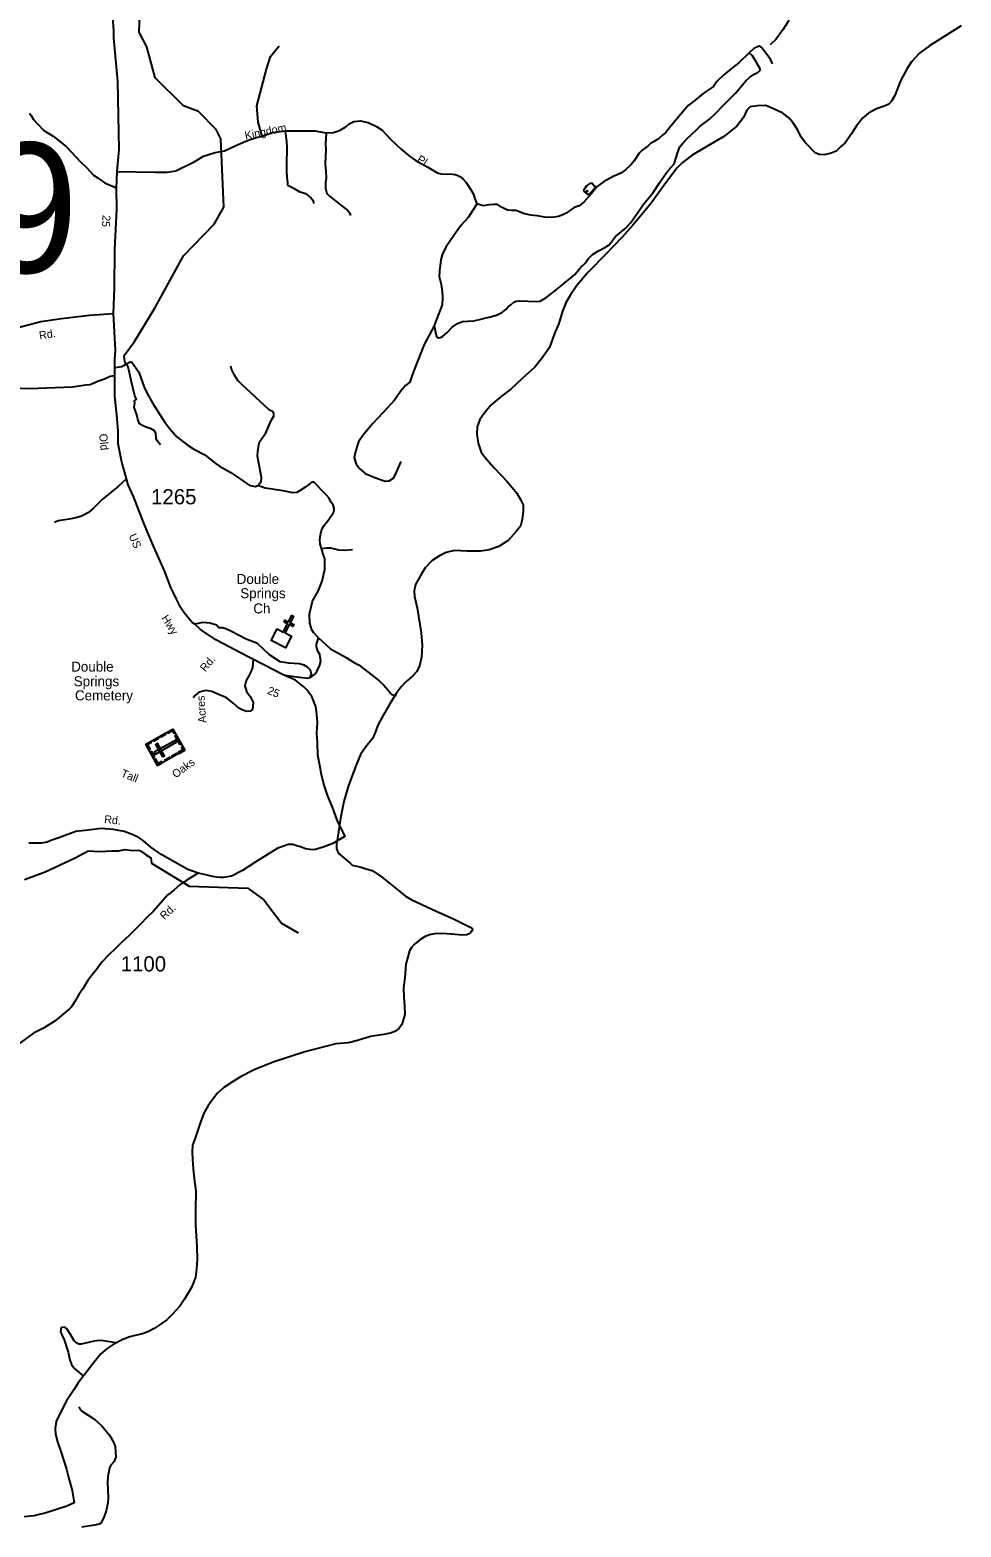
# Model space of a CAD drawing. Extents: x 884530 to 1028605, y 526725 to 653634.
# Drawn here: x 973414 to 981047, y 533743 to 546021 of the extents above; entities that cross this region are included whole.
import ezdxf

# ---------------------------------------------------------------- set-up
doc = ezdxf.new("R2010")
doc.units = 0
for name, color, linetype in [('Exist Boundary Political StateLine', 7, 'Continuous'), ('Exist Civil Recreational Trail or Greenway National Park', 7, 'Continuous'), ('Exist Cultural Cemetery CELL', 7, 'Continuous'), ('Exist Cultural Cemetery Label', 7, 'Continuous'), ('Exist Cultural Church CELL', 7, 'Continuous'), ('Exist Cultural Church Label', 7, 'Continuous'), ('Exist Hydrographic Creek Single Shore', 7, 'Continuous'), ('Exist Hydrographic Pond Under 1500 Sq Ft', 7, 'Continuous'), ('Exist Road Non-System Type 51', 7, 'Continuous'), ('Exist Road Non-System Type 51 Label', 7, 'Continuous'), ('Exist Road Primary NC Attributed', 7, 'Continuous'), ('Exist Road Secondary Structure Standard Bridge Number Label', 7, 'Continuous'), ('Exist Road Secondary Type 51 Attributed', 7, 'Continuous'), ('Exist Road Secondary Type 51 Label', 7, 'Continuous'), ('Exist Road Secondary Type 51 Number Label', 7, 'Continuous')]:
    doc.layers.add(name, color=color, linetype=linetype)

msp = doc.modelspace()

# ---------------------------------------------------------------- linework, layer by layer
at = {"layer": 'Exist Boundary Political StateLine'}
for points in [[(981047, 546056), (980900, 545961), (980789, 545891), (980707, 545830), (980640, 545760), (980605, 545705), (980551, 545603), (980503, 545483), (980477, 545438), (980456, 545414), (980426, 545399), (980353, 545374), (980288, 545340), (980238, 545298), (980215, 545266), (980190, 545235), (980150, 545169), (980097, 545096), (980058, 545062), (980023, 545027), (979982, 545010), (979925, 544996), (979884, 545000), (979852, 545013), (979773, 545096), (979737, 545143), (979709, 545200), (979669, 545263), (979632, 545303), (979587, 545340), (979510, 545375), (979447, 545401), (979377, 545400), (979319, 545390), (979292, 545364), (979264, 545303), (979209, 545233), (979102, 545147), (978957, 545064), (978843, 544994), (978763, 544934), (978721, 544890), (978627, 544767), (978499, 544591), (978357, 544420), (978269, 544323), (978132, 544180)], [(978132, 544180), (977993, 544037), (977897, 543926), (977845, 543849), (977808, 543783), (977780, 543716), (977750, 543613), (977713, 543532), (977673, 543417), (977615, 543335), (977552, 543255), (977446, 543159), (977355, 543074), (977280, 543018), (977191, 542944), (977134, 542872), (977101, 542827), (977081, 542767), (977078, 542705), (977088, 542633), (977113, 542560), (977142, 542517), (977217, 542432), (977327, 542318), (977404, 542222), (977436, 542170), (977457, 542128), (977457, 542076), (977449, 542006), (977435, 541952), (977399, 541908), (977334, 541834), (977257, 541785), (977178, 541757), (977107, 541746), (976997, 541747), (976893, 541751), (976827, 541735), (976770, 541709), (976712, 541671), (976654, 541609), (976625, 541562), (976574, 541474), (976564, 541422), (976566, 541374), (976587, 541283), (976622, 541078), (976630, 540976), (976623, 540878), (976606, 540806), (976585, 540759), (976552, 540724), (976496, 540674), (976456, 540633), (976415, 540579), (976364, 540494), (976300, 540385), (976266, 540320), (976250, 540274), (976226, 540213), (976167, 540141), (976125, 540078), (976086, 539986), (976022, 539818), (975988, 539693), (975961, 539558), (975943, 539442), (975926, 539343), (975928, 539309), (975934, 539287), (975951, 539262), (976038, 539187), (976056, 539172), (976081, 539167), (976129, 539156), (976179, 539140), (976218, 539127), (976296, 539076), (976347, 539036), (976450, 538954), (976493, 538917), (976538, 538889), (976708, 538811), (976897, 538725), (977023, 538664), (977042, 538650), (977037, 538630), (977019, 538610), (976996, 538601), (976962, 538598), (976867, 538606), (976793, 538610), (976729, 538608), (976690, 538600), (976654, 538587), (976611, 538559), (976566, 538524)], [(976566, 538524), (976543, 538497), (976524, 538468), (976514, 538428), (976496, 538361), (976486, 538247), (976477, 538165), (976480, 538089), (976484, 538019), (976488, 537947), (976463, 537865), (976442, 537834), (976411, 537811), (976378, 537796), (976316, 537784), (976205, 537766), (976100, 537734), (976025, 537714), (975921, 537706), (975666, 537641), (975409, 537556), (975253, 537493), (975139, 537437), (975073, 537395), (975002, 537348), (974948, 537299), (974904, 537241), (974873, 537194), (974840, 537137), (974812, 537064), (974772, 536941), (974747, 536876), (974743, 536822), (974747, 536758), (974753, 536682), (974763, 536577), (974774, 536501), (974775, 536459), (974770, 536377), (974771, 536223), (974781, 536044), (974785, 535938), (974778, 535860), (974770, 535790), (974737, 535709), (974680, 535613), (974642, 535555), (974583, 535489), (974536, 535444), (974474, 535398), (974433, 535372), (974390, 535349), (974344, 535331), (974233, 535303), (974174, 535281), (974096, 535241), (974047, 535209), (973996, 535163), (973941, 535095), (973809, 534925), (973778, 534876), (973714, 534778), (973674, 534704), (973630, 534609), (973620, 534553), (973623, 534505), (973640, 534443), (973671, 534355), (973713, 534218), (973732, 534141), (973759, 534042), (973777, 533941), (973716, 533916), (973548, 533859), (973447, 533835), (973367, 533826)]]:
    msp.add_lwpolyline(points, dxfattribs=at)
at = {"layer": 'Exist Civil Recreational Trail or Greenway National Park'}
msp.add_lwpolyline([(979635, 546099), (979585, 546021), (979528, 545943), (979483, 545898)], dxfattribs=at)
at = {"layer": 'Exist Cultural Cemetery CELL'}
for points in [[(974460, 539990), (974363, 540164), (974586, 540288), (974683, 540114)], [(974528, 540243), (974490, 540222), (974485, 540231), (974523, 540253)], [(974602, 540259), (974592, 540253), (974581, 540272), (974546, 540253), (974540, 540262), (974586, 540288)], [(974645, 540158), (974603, 540232), (974613, 540238), (974655, 540164)], [(974401, 540185), (974407, 540175), (974378, 540159), (974398, 540124), (974388, 540119), (974363, 540164)], [(974470, 540211), (974433, 540189), (974427, 540199), (974465, 540220)], [(974433, 540099), (974442, 540083), (974619, 540182), (974610, 540198)], [(974500, 540059), (974516, 540068), (974459, 540171), (974442, 540162)], [(974666, 540143), (974656, 540137), (974667, 540118), (974632, 540098), (974637, 540088), (974683, 540114)], [(974424, 540055), (974399, 540100), (974409, 540105), (974434, 540060)], [(974498, 540011), (974492, 540021), (974464, 540005), (974445, 540041), (974435, 540035), (974460, 539990)], [(974563, 540047), (974525, 540026), (974519, 540036), (974557, 540057)], [(974621, 540080), (974584, 540059), (974578, 540069), (974616, 540090)]]:
    msp.add_lwpolyline(points, close=True, dxfattribs=at)
at = {"layer": 'Exist Cultural Church CELL'}
msp.add_lwpolyline([(975440, 541109), (975491, 541083), (975526, 541151), (975497, 541166), (975504, 541180), (975533, 541166), (975560, 541219), (975574, 541212), (975547, 541158), (975576, 541144), (975568, 541130), (975540, 541144), (975505, 541076), (975557, 541050), (975508, 540955), (975392, 541014)], close=True, dxfattribs=at)
at = {"layer": 'Exist Hydrographic Creek Single Shore'}
for points in [[(974485, 542618), (974456, 542652), (974448, 542671), (974447, 542715), (974436, 542733), (974401, 542753), (974371, 542761), (974348, 542772), (974332, 542781), (974312, 542791), (974298, 542829), (974291, 542864), (974280, 542894), (974267, 542928), (974275, 542960), (974272, 542979), (974286, 542992), (974274, 543021), (974243, 543146), (974226, 543222), (974218, 543255), (974195, 543291), (974188, 543323), (974185, 543351), (974272, 543466), (974441, 543745), (974672, 544170), (974923, 544428), (975003, 544567), (974980, 545129), (974941, 545205), (974796, 545352), (974673, 545398), (974439, 545629), (974373, 545883), (974310, 546002), (974329, 546543)], [(973369, 539054), (973538, 539116), (973784, 539233), (973891, 539290), (973988, 539285), (974086, 539289), (974142, 539288), (974188, 539299), (974256, 539292), (974303, 539295), (974319, 539289), (974361, 539258), (974405, 539232), (974410, 539188), (974718, 539000), (975201, 538984), (975331, 538886), (975475, 538696), (975614, 538618)]]:
    msp.add_lwpolyline(points, dxfattribs=at)
at = {"layer": 'Exist Hydrographic Pond Under 1500 Sq Ft'}
msp.add_lwpolyline([(977957, 544696), (977955, 544712), (977967, 544729), (977976, 544742), (977988, 544748), (977999, 544756), (978007, 544764), (978022, 544766), (978032, 544754), (978038, 544744), (978049, 544735), (978047, 544727), (978036, 544714), (978018, 544692), (978007, 544683), (977999, 544675), (977992, 544673), (977984, 544673), (977972, 544685), (977986, 544698), (977978, 544704), (977965, 544692)], close=True, dxfattribs=at)
at = {"layer": 'Exist Road Non-System Type 51'}
for points in [[(975318, 545151), (975284, 545266), (975275, 545398), (975352, 545700), (975387, 545804), (975457, 545890)], [(979310, 545833), (979353, 545875), (979378, 545885), (979393, 545891), (979412, 545881), (979458, 545821), (979480, 545789), (979499, 545744)], [(979310, 545833), (979224, 545752), (979166, 545704), (979101, 545654), (979045, 545598), (979018, 545558), (978953, 545514), (978916, 545487), (978866, 545446), (978809, 545402), (978749, 545331), (978691, 545262), (978645, 545206), (978626, 545181), (978603, 545160), (978572, 545135), (978553, 545119), (978530, 545106), (978501, 545089), (978478, 545067), (978453, 545048), (978430, 545033), (978407, 545010), (978368, 544948), (978343, 544919), (978297, 544873), (978257, 544848), (978195, 544819), (978117, 544775), (978065, 544737), (978017, 544681), (977955, 544610), (977917, 544579), (977876, 544564), (977838, 544537), (977811, 544519), (977782, 544506), (977746, 544492), (977692, 544483), (977636, 544485), (977571, 544496), (977517, 544502), (977461, 544516), (977399, 544541), (977361, 544541), (977328, 544544), (977280, 544567), (977246, 544591), (977215, 544589), (977178, 544587), (977128, 544579), (977076, 544596)], [(977701, 543867), (977770, 543923), (977882, 544017), (977930, 544075), (977949, 544092), (977965, 544108), (977992, 544146), (978026, 544181), (978076, 544210), (978132, 544241), (978163, 544258), (978215, 544327), (978247, 544354), (978299, 544396), (978341, 544442), (978393, 544516), (978443, 544592), (978474, 544629), (978524, 544687), (978574, 544767), (978620, 544835), (978649, 544871), (978695, 544923), (978724, 545019), (978741, 545062), (978766, 545094), (978799, 545127), (978841, 545167), (978880, 545204), (978907, 545233), (978951, 545264), (978986, 545289), (979035, 545335), (979099, 545404), (979197, 545504), (979283, 545604), (979314, 545631), (979357, 545662), (979385, 545675), (979399, 545691), (979399, 545702), (979382, 545735), (979362, 545768), (979337, 545810), (979310, 545833)], [(973411, 545340), (973423, 545320), (973443, 545287), (973476, 545250), (973528, 545196), (973603, 545150), (973712, 545066), (973827, 544940), (973877, 544893), (973936, 544830), (973974, 544806), (974004, 544785), (974028, 544768), (974062, 544752), (974098, 544738), (974124, 544723)], [(975842, 545177), (975902, 545181), (975951, 545196), (976003, 545227), (976032, 545251), (976070, 545271), (976121, 545275), (976187, 545261), (976256, 545230), (976301, 545199), (976367, 545129), (976461, 545041), (976526, 544985), (976572, 544954), (976677, 544897), (976743, 544854), (976761, 544847), (976785, 544842), (976879, 544839), (976899, 544835), (976916, 544830), (976944, 544816), (976965, 544798), (976989, 544769), (977032, 544706), (977049, 544674), (977061, 544635), (977076, 544596)], [(974130, 544861), (974438, 544854), (974539, 544854), (974610, 544865), (974761, 544941), (974837, 544985), (974932, 545016), (975009, 545031), (975091, 545067), (975102, 545073), (975165, 545100), (975211, 545121), (975271, 545140), (975318, 545151)], [(975318, 545151), (975401, 545179), (975507, 545194)], [(975507, 545194), (975750, 545195), (975842, 545177)], [(975507, 545194), (975517, 545104), (975519, 545061), (975521, 545012), (975517, 544963), (975516, 544906), (975517, 544860), (975519, 544814), (975524, 544769), (975526, 544752), (975532, 544745), (975544, 544740), (975574, 544723), (975622, 544697), (975672, 544679), (975701, 544659), (975718, 544643), (975733, 544624), (975741, 544599)], [(975842, 545177), (975837, 545088), (975839, 545039), (975838, 544989), (975834, 544920), (975839, 544861), (975841, 544805), (975836, 544769), (975838, 544724), (975849, 544681), (975866, 544661), (975921, 544618), (975961, 544588), (975999, 544556), (976020, 544540), (976036, 544520), (976042, 544500)], [(977076, 544596), (977052, 544555), (977005, 544482), (976949, 544421), (976888, 544336), (976824, 544239), (976794, 544176), (976781, 544137), (976772, 544045), (976769, 544000), (976785, 543934), (976792, 543875), (976797, 543830), (976792, 543768), (976728, 543597)], [(976728, 543597), (976743, 543515), (976751, 543501), (976762, 543495), (976777, 543499), (976793, 543505), (976834, 543539), (976876, 543583), (976920, 543614), (976961, 543630), (977001, 543633), (977053, 543637), (977122, 543651), (977176, 543665), (977239, 543682), (977287, 543706), (977318, 543731), (977338, 543752), (977357, 543767), (977381, 543788), (977401, 543796), (977428, 543801), (977570, 543793), (977596, 543797), (977642, 543825), (977701, 543867)], [(976728, 543597), (976724, 543589), (976646, 543443), (976577, 543270), (976549, 543197), (976527, 543132), (976493, 543106), (976452, 543056), (976402, 542984), (976307, 542881), (976223, 542792), (976143, 542696), (976108, 542644), (976094, 542600), (976080, 542554), (976071, 542513), (976087, 542461), (976118, 542422), (976161, 542385), (976242, 542351), (976272, 542341), (976300, 542330), (976325, 542321), (976360, 542323), (976397, 542348), (976418, 542394), (976457, 542483)], [(974111, 543253), (974167, 543261), (974178, 543268), (974212, 543285), (974229, 543297), (974240, 543300), (974250, 543298), (974306, 543214), (974349, 543093), (974377, 543035), (974420, 542958), (974516, 542808), (974564, 542746), (974618, 542685), (974703, 542618), (974756, 542584), (974847, 542536), (974932, 542469), (974968, 542444), (975060, 542391), (975210, 542288), (975259, 542276), (975282, 542284)], [(974109, 543186), (974071, 543178), (974024, 543157), (973975, 543141), (973907, 543111), (973872, 543107), (973763, 543093), (973410, 543078), (973188, 543087), (973131, 543079), (972994, 543027), (972920, 542996), (972852, 542956), (972732, 542850), (972663, 542765), (972624, 542694), (972601, 542621), (972578, 542588), (972558, 542551)], [(975282, 542284), (975308, 542319), (975313, 542350), (975278, 542527), (975281, 542564), (975290, 542619), (975297, 542643), (975348, 542716), (975394, 542824), (975412, 542854), (975412, 542875), (975401, 542893), (975379, 542904), (975147, 543116), (975118, 543146), (975090, 543189), (975067, 543239), (975060, 543265)], [(974204, 542341), (974137, 542278), (974096, 542243), (974005, 542170), (973934, 542099), (973895, 542065), (973859, 542044), (973831, 542030), (973789, 542019), (973734, 542009), (973664, 541998), (973648, 541995), (973631, 541989), (973616, 541982)], [(975804, 541769), (975793, 541808), (975791, 541839), (975797, 541881), (975804, 541917), (975819, 541953), (975842, 541978), (975862, 542005), (975887, 542039), (975903, 542065), (975908, 542085), (975907, 542097), (975899, 542126), (975884, 542146), (975868, 542182), (975846, 542207), (975807, 542244), (975774, 542281), (975750, 542308), (975739, 542316), (975726, 542313), (975676, 542274), (975630, 542245), (975601, 542228), (975568, 542224), (975491, 542241), (975380, 542259), (975343, 542264), (975282, 542284)], [(975780, 541037), (975738, 541079), (975725, 541101), (975707, 541155), (975705, 541231), (975729, 541338), (975776, 541419), (975810, 541502), (975830, 541597), (975830, 541684), (975829, 541693), (975826, 541701), (975818, 541722), (975811, 541738), (975809, 541752), (975804, 541769)], [(975804, 541769), (975848, 541775), (975878, 541774), (975942, 541758), (975994, 541756), (976059, 541761)], [(975709, 540712), (975721, 540738), (975713, 540772), (975690, 540795), (975662, 540812), (975622, 540824), (975536, 540827), (975465, 540840), (975379, 540897), (975278, 540990), (975185, 541025), (975062, 541091), (975020, 541111), (974992, 541117), (974963, 541119), (974942, 541141), (974890, 541155), (974832, 541161), (974766, 541147)], [(975709, 540712), (975725, 540718), (975748, 540738), (975765, 540760), (975788, 540805), (975798, 540843), (975790, 540899), (975781, 540914), (975774, 540927), (975768, 540940), (975764, 540965), (975764, 540983), (975772, 541009), (975780, 541037)], [(975780, 541037), (975879, 540946), (975901, 540932), (975933, 540915), (976006, 540875), (976067, 540837), (976113, 540813), (976151, 540781), (976187, 540755), (976235, 540715), (976277, 540682), (976315, 540647), (976350, 540608), (976366, 540584), (976380, 540571), (976398, 540566), (976420, 540564)], [(975245, 540860), (975238, 540794), (975225, 540758), (975207, 540724), (975185, 540685), (975175, 540641), (975189, 540597), (975221, 540552), (975245, 540507), (975239, 540448), (975220, 540435), (975192, 540433), (975160, 540442), (975126, 540458), (975079, 540500), (975023, 540547), (974974, 540565), (974906, 540595), (974854, 540604), (974819, 540597), (974793, 540585), (974770, 540565), (974751, 540545)], [(975501, 540730), (975646, 540711), (975692, 540705), (975709, 540712)], [(974118, 535253), (974016, 535270), (973983, 535273), (973940, 535269), (973834, 535243), (973814, 535244), (973794, 535254), (973776, 535270), (973747, 535322), (973715, 535370), (973700, 535382), (973677, 535381), (973671, 535376), (973667, 535367), (973665, 535346), (973672, 535324), (973694, 535280), (973728, 535178), (973742, 535114), (973754, 535077), (973766, 535059), (973783, 535041), (973854, 534982)], [(973814, 534728), (973826, 534707), (973836, 534697), (973946, 534625), (974004, 534573), (974067, 534497), (974102, 534435), (974112, 534403), (974117, 534317), (974111, 534297), (974103, 534282), (974076, 534250), (974067, 534230), (974052, 534155), (974049, 534114), (974054, 533981), (974053, 533942), (974038, 533876), (974020, 533821), (973995, 533776), (973981, 533768), (973944, 533758), (973840, 533743)]]:
    msp.add_lwpolyline(points, dxfattribs=at)
at = {"layer": 'Exist Road Primary NC Attributed'}
for points in [[(974099, 543696), (974106, 543903), (974111, 544221), (974126, 544551), (974124, 544723), (974130, 544861), (974145, 545040), (974133, 545598), (974101, 545957), (974101, 546011), (974090, 546173)], [(970481, 541776), (970638, 541880), (970778, 541978), (970915, 542066), (971072, 542174), (971129, 542216), (971197, 542260), (971996, 542811), (972206, 542958), (972688, 543279), (972852, 543373), (972966, 543433), (973284, 543572), (973502, 543629), (973673, 543655), (973902, 543681), (974099, 543696)]]:
    msp.add_lwpolyline(points, dxfattribs=at)
at = {"layer": 'Exist Road Secondary Type 51 Attributed'}
for points in [[(975997, 539410), (975938, 539528), (975894, 539646), (975857, 539738), (975825, 539828), (975805, 539912), (975793, 539975), (975774, 540074), (975770, 540178), (975767, 540253), (975772, 540342), (975765, 540411), (975757, 540474), (975724, 540555), (975685, 540610), (975660, 540635), (975591, 540690), (975485, 540734), (975341, 540809), (975203, 540880), (974939, 541020), (974812, 541105), (974766, 541147), (974744, 541163), (974727, 541180), (974679, 541240), (974650, 541283), (974616, 541353), (974589, 541411), (974570, 541450), (974517, 541585), (974419, 541806), (974353, 541964), (974263, 542196), (974220, 542292), (974204, 542341), (974184, 542418), (974168, 542477), (974137, 542626), (974137, 542730), (974130, 542834), (974111, 543018), (974109, 543186), (974111, 543253), (974110, 543322), (974114, 543394), (974099, 543696)], [(974793, 539106), (974709, 539136), (974496, 539256), (974406, 539319), (974342, 539374), (974301, 539401), (974251, 539423), (974185, 539447), (974100, 539464), (973997, 539471), (973892, 539460), (973789, 539449), (973651, 539397), (973593, 539376), (973554, 539361), (973508, 539352), (973474, 539352), (973404, 539352)], [(975997, 539410), (975897, 539350), (975817, 539320), (975745, 539298), (975712, 539299), (975674, 539306), (975640, 539318), (975610, 539327), (975569, 539341), (975531, 539340), (975509, 539334), (975446, 539312), (975353, 539253), (975265, 539200), (975155, 539129), (975065, 539082), (975001, 539071), (974974, 539070), (974942, 539074), (974900, 539082), (974856, 539091), (974793, 539106)], [(974793, 539106), (974694, 539045), (974642, 539010), (974595, 538969), (974564, 538942), (974545, 538927), (974426, 538795), (974372, 538742), (974323, 538690), (974226, 538595), (974165, 538538), (974117, 538490), (974055, 538430), (974002, 538375), (973950, 538305), (973925, 538271), (973887, 538227), (973847, 538158), (973815, 538112), (973781, 538053), (973754, 538011), (973739, 537994), (973621, 537896), (973525, 537836), (973442, 537795), (973312, 537697)]]:
    msp.add_lwpolyline(points, dxfattribs=at)

# ---------------------------------------------------------------- texts
at = {"layer": 'Exist Cultural Cemetery Label'}
for s, p in [('Double', (973752, 540759)), ('Springs', (973773, 540639)), ('Cemetery', (973783, 540523))]:
    msp.add_text(s, height=82, dxfattribs=at).set_placement(p)
at = {"layer": 'Exist Cultural Church Label'}
for s, p in [('Double', (975109, 541478)), ('Springs', (975138, 541361)), ('Ch', (975245, 541236))]:
    msp.add_text(s, height=82, dxfattribs=at).set_placement(p)
at = {"layer": 'Exist Road Non-System Type 51 Label'}
for s, rotation, p in [('Kingdom', 11.6966, (975182, 545122)), ('Pl.', 328.0438, (976580, 544944)), ('Rd.', 50.7197, (974852, 540752)), ('Acres', 94.0236, (974860, 540340)), ('Oaks', 36.0363, (974608, 539882)), ('Tall', 338.4921, (974154, 539900))]:
    msp.add_text(s, height=65.6, rotation=rotation, dxfattribs=at).set_placement(p)
at = {"layer": 'Exist Road Secondary Structure Standard Bridge Number Label'}
msp.add_text('69', height=1066.3, dxfattribs=at).set_placement((972225, 544030))
at = {"layer": 'Exist Road Secondary Type 51 Label'}
for s, rotation, p in [('25', 265.6815, (974010, 544505)), ('Rd.', 9.0306, (973494, 543482)), ('Old', 275.8266, (973981, 542707)), ('US', 293.2071, (974222, 541874)), ('Hwy', 302.4221, (974488, 541198)), ('25', 337.9017, (975354, 540579)), ('Rd.', 354.1672, (974020, 539517)), ('Rd.', 43.0982, (974516, 538720))]:
    msp.add_text(s, height=65.6, rotation=rotation, dxfattribs=at).set_placement(p)
at = {"layer": 'Exist Road Secondary Type 51 Number Label'}
for s, p in [('1265', (974407, 542131)), ('1100', (974158, 538300))]:
    msp.add_text(s, height=125, dxfattribs=at).set_placement(p)

doc.saveas('drawing.dxf')
